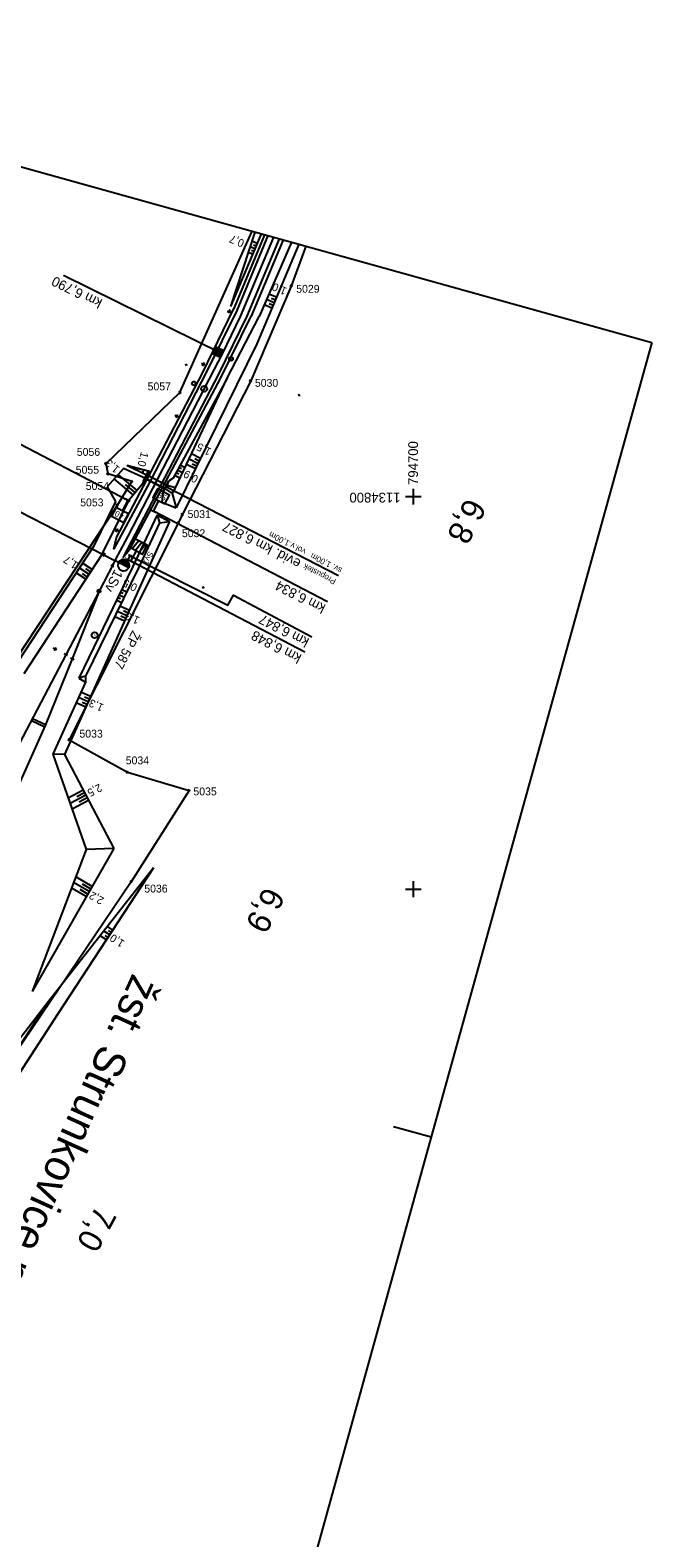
# Model space of a CAD drawing. Extents: x -795094 to -794639, y -1135368 to -1134681.
# Drawn here: x -794797.7 to -794639.2, y -1135065.2 to -1134681.2 of the extents above; entities that cross this region are included whole.
import ezdxf

# ---------------------------------------------------------------- set-up
doc = ezdxf.new("R2010")
doc.units = 0
for name, color, linetype in [('0381KM005-009P - Vrstva 1', 7, 'Continuous'), ('0381KM005-009P - Vrstva 19', 7, 'Continuous'), ('0381KM005-009P - Vrstva 2', 7, 'Continuous'), ('0381KM005-009P - Vrstva 23', 7, 'Continuous'), ('0381KM005-009P - Vrstva 28', 7, 'Continuous'), ('0381KM005-009P - Vrstva 3', 7, 'Continuous'), ('0381KM005-009P - Vrstva 33', 7, 'Continuous'), ('0381KM005-009P - Vrstva 4', 7, 'Continuous'), ('0381KM005-009P - Vrstva 48', 7, 'Continuous'), ('0381KM005-009P - Vrstva 49', 7, 'Continuous'), ('0381KM005-009P - Vrstva 5', 7, 'Continuous'), ('0381KM005-009P - Vrstva 51', 7, 'Continuous'), ('0381KM005-009P - Vrstva 6', 7, 'Continuous'), ('0381KM005-009P - Vrstva 7', 7, 'Continuous'), ('formát', 7, 'Continuous'), ('krizky_1000 - souradnice', 7, 'Continuous'), ('krizky_1000 - Vrstva 1', 7, 'Continuous'), ('szdc - hran DP', 7, 'Continuous'), ('szdc - szdc_cislo', 7, 'Continuous'), ('szdc - szdc_krizek', 7, 'Continuous'), ('vyt_sit - stávající', 7, 'Continuous')]:
    doc.layers.add(name, color=color, linetype=linetype)

msp = doc.modelspace()

# ---------------------------------------------------------------- linework, layer by layer
at = {"layer": '0381KM005-009P - Vrstva 1'}
for points in [[(-794735.66, -1134733.94), (-794744.1, -1134754.13), (-794748.76, -1134763.69), (-794750.73, -1134767.6), (-794757.62, -1134780.92)], [(-794757.62, -1134780.92), (-794772.8, -1134810.07), (-794776.07, -1134816.32)], [(-794776.07, -1134816.32), (-794776.43, -1134817.02), (-794780.11, -1134824.07), (-794788.58, -1134840.28)], [(-794776.07, -1134816.32), (-794776.43, -1134817.02), (-794780.11, -1134824.07), (-794786.96, -1134841.36)], [(-794788.58, -1134840.28), (-794803.19, -1134868.16), (-794810.38, -1134881.86), (-794818.66, -1134897.6), (-794826.62, -1134912.5), (-794834.33, -1134926.85), (-794861.92, -1134977.99)], [(-794786.96, -1134841.36), (-794793.84, -1134858.32), (-794800.91, -1134874.12), (-794807.73, -1134887.87), (-794826.52, -1134924.29), (-794833.34, -1134937.13), (-794839.37, -1134947.86), (-794840.75, -1134950.16), (-794846.08, -1134958.61), (-794850.88, -1134965.55), (-794860.1, -1134978.74)]]:
    msp.add_lwpolyline(points, dxfattribs=at)
at = {"layer": '0381KM005-009P - Vrstva 19'}
for p, q in [((-794767.26, -1134793.5), (-794768.87, -1134796.52)), ((-794768.87, -1134796.52), (-794768.27, -1134795.41)), ((-794768.27, -1134795.41), (-794767.82, -1134794.57)), ((-794768.27, -1134795.41), (-794768.27, -1134795.41)), ((-794763.3, -1134797.99), (-794768.27, -1134795.41)), ((-794768.27, -1134795.41), (-794763.33, -1134798.06)), ((-794767.82, -1134794.57), (-794767.26, -1134793.5)), ((-794767.82, -1134794.57), (-794767.82, -1134794.57)), ((-794762.85, -1134797.19), (-794767.82, -1134794.57)), ((-794762.89, -1134797.15), (-794767.82, -1134794.57)), ((-794763.85, -1134798.98), (-794762.37, -1134796.11)), ((-794763.3, -1134797.99), (-794763.85, -1134798.98)), ((-794762.89, -1134797.15), (-794763.33, -1134798.06)), ((-794763.33, -1134798.06), (-794763.3, -1134797.99)), ((-794719.1, -1134820.2), (-794763.06, -1134797.51)), ((-794762.85, -1134797.19), (-794762.89, -1134797.15)), ((-794762.37, -1134796.11), (-794762.85, -1134797.19))]:
    msp.add_line(p, q, dxfattribs=at)
at = {"layer": '0381KM005-009P - Vrstva 2'}
for p, q in [((-794815.95, -1134795.81), (-794776.07, -1134816.32)), ((-794775.14, -1134816.79), (-794776.07, -1134816.32)), ((-794772.54, -1134818.13), (-794775.14, -1134816.79)), ((-794774.93, -1134816.49), (-794774.77, -1134816.98)), ((-794774.61, -1134816.22), (-794774.29, -1134817.23)), ((-794774.26, -1134816.06), (-794773.81, -1134817.48)), ((-794773.89, -1134816), (-794773.33, -1134817.72)), ((-794773.47, -1134816.05), (-794772.86, -1134817.97)), ((-794773, -1134816.26), (-794772.46, -1134817.95)), ((-794772.54, -1134818.13), (-794772.54, -1134818.13)), ((-794780.11, -1134824.07), (-794786.96, -1134841.36)), ((-794788.14, -1134840.51), (-794789.03, -1134840.05)), ((-794786.49, -1134841.55), (-794787.42, -1134841.18))]:
    msp.add_line(p, q, dxfattribs=at)
for points in [[(-794776.07, -1134816.32), (-794776.43, -1134817.02), (-794780.11, -1134824.07), (-794788.58, -1134840.28)], [(-794776.64, -1134817.99), (-794776.43, -1134817.02), (-794777.1, -1134817.76)]]:
    msp.add_lwpolyline(points, dxfattribs=at)
msp.add_circle((-794780.11, -1134824.07), 0.4, dxfattribs=at)
for start, end in [(152.7102, 333.1797), (332.7997, 152.7606)]:
    msp.add_arc((-794773.84, -1134817.46), 1.46, start, end, dxfattribs=at)
at = {"layer": '0381KM005-009P - Vrstva 28'}
msp.add_line((-794746.44, -1134764.88), (-794746.48, -1134764.97), dxfattribs=at)
msp.add_circle((-794746.46, -1134764.93), 0.5, dxfattribs=at)
at = {"layer": '0381KM005-009P - Vrstva 3'}
for p, q in [((-794748.76, -1134763.69), (-794789.21, -1134743.71)), ((-794750.81, -1134763.35), (-794750.63, -1134763.89)), ((-794750.58, -1134762.87), (-794750.15, -1134764.12)), ((-794750.35, -1134762.39), (-794749.67, -1134764.36)), ((-794750.12, -1134761.92), (-794749.2, -1134764.59)), ((-794749.64, -1134762.15), (-794748.96, -1134764.11)), ((-794749.16, -1134762.38), (-794748.73, -1134763.64)), ((-794748.69, -1134762.61), (-794748.5, -1134763.16))]:
    msp.add_line(p, q, dxfattribs=at)
msp.add_lwpolyline([(-794748.32, -1134762.79), (-794749.2, -1134764.59), (-794750.99, -1134763.71), (-794750.12, -1134761.92)], close=True, dxfattribs=at)
at = {"layer": '0381KM005-009P - Vrstva 33'}
msp.add_line((-794768.83, -1134796.2), (-794767.55, -1134793.7), dxfattribs=at)
at = {"layer": '0381KM005-009P - Vrstva 4'}
for points in [[(-794737.95, -1134733.31), (-794745.79, -1134752.29)], [(-794737.06, -1134733.55), (-794744.97, -1134752.65)], [(-794734.21, -1134734.35), (-794742.45, -1134754.09)], [(-794733.14, -1134734.64), (-794741.33, -1134754.03)], [(-794744.97, -1134752.65), (-794752.57, -1134767.89), (-794767.17, -1134796.25), (-794776.32, -1134813.35), (-794775.69, -1134810.46), (-794767.89, -1134795.76), (-794753.75, -1134768.59), (-794745.79, -1134752.29)], [(-794742.45, -1134754.09), (-794749.67, -1134768.83), (-794764.43, -1134797.23), (-794773.98, -1134815.47), (-794772.27, -1134813.39), (-794763.8, -1134797.42), (-794749.03, -1134769.75), (-794741.33, -1134754.03)]]:
    msp.add_lwpolyline(points, dxfattribs=at)
at = {"layer": '0381KM005-009P - Vrstva 48'}
for p, q in [((-794740.39, -1134736.92), (-794741.61, -1134736.4)), ((-794740.68, -1134737.61), (-794741.26, -1134737.36)), ((-794739.8, -1134735.54), (-794741.14, -1134734.97)), ((-794740.09, -1134736.23), (-794740.73, -1134735.96)), ((-794740.97, -1134738.3), (-794742.08, -1134737.83)), ((-794734.87, -1134749.26), (-794736.81, -1134748.45)), ((-794736.03, -1134752.03), (-794738.01, -1134751.2)), ((-794735.45, -1134750.65), (-794737.41, -1134749.82)), ((-794735.74, -1134751.34), (-794736.72, -1134750.92)), ((-794735.16, -1134749.96), (-794736.13, -1134749.54)), ((-794754.88, -1134791.63), (-794757.17, -1134790.5)), ((-794754.22, -1134790.28), (-794756.53, -1134789.14)), ((-794754.55, -1134790.95), (-794755.7, -1134790.39)), ((-794770.44, -1134798.41), (-794775.25, -1134794.4)), ((-794770.26, -1134792.73), (-794770.4, -1134793.3)), ((-794769.53, -1134792.91), (-794769.62, -1134793.27)), ((-794768.8, -1134793.1), (-794769.03, -1134793.97)), ((-794760.82, -1134794.53), (-794759.43, -1134795.29)), ((-794760.46, -1134793.87), (-794759.79, -1134794.24)), ((-794760.11, -1134793.21), (-794758.79, -1134793.93)), ((-794759.75, -1134792.55), (-794759.11, -1134792.9)), ((-794759.39, -1134791.89), (-794758.15, -1134792.57)), ((-794755.55, -1134792.97), (-794757.81, -1134791.86)), ((-794755.21, -1134792.3), (-794756.35, -1134791.74)), ((-794771.4, -1134799.56), (-794776.25, -1134795.52)), ((-794770.92, -1134798.98), (-794773.33, -1134796.97)), ((-794782.69, -1134819.79), (-794785.16, -1134818.18)), ((-794781.87, -1134818.54), (-794784.33, -1134816.93)), ((-794782.28, -1134819.17), (-794783.51, -1134818.36)), ((-794783.51, -1134821.05), (-794785.98, -1134819.43)), ((-794783.1, -1134820.42), (-794784.34, -1134819.61)), ((-794775.3, -1134825.69), (-794774.65, -1134826)), ((-794774.98, -1134825.01), (-794773.67, -1134825.64)), ((-794774.65, -1134824.34), (-794774, -1134824.65)), ((-794774.33, -1134823.66), (-794773.01, -1134824.29)), ((-794775.63, -1134826.36), (-794774.33, -1134826.99)), ((-794773.01, -1134830.36), (-794775.45, -1134829.27)), ((-794772.39, -1134828.99), (-794774.79, -1134827.92)), ((-794772.7, -1134829.68), (-794773.91, -1134829.14)), ((-794773.62, -1134831.73), (-794776.11, -1134830.61)), ((-794773.32, -1134831.05), (-794774.55, -1134830.49)), ((-794783.49, -1134853.67), (-794785.97, -1134852.55)), ((-794782.87, -1134852.3), (-794785.35, -1134851.19)), ((-794782.26, -1134850.93), (-794784.73, -1134849.82)), ((-794783.18, -1134852.98), (-794784.42, -1134852.43)), ((-794782.56, -1134851.61), (-794783.8, -1134851.06)), ((-794784.18, -1134874.77), (-794788, -1134876.78)), ((-794783.83, -1134875.43), (-794785.79, -1134876.46)), ((-794783.48, -1134876.09), (-794787.5, -1134878.21)), ((-794782.78, -1134877.42), (-794787, -1134879.64)), ((-794783.13, -1134876.76), (-794785.19, -1134877.84)), ((-794782.63, -1134900.58), (-794786.61, -1134898.31)), ((-794781.89, -1134899.28), (-794786.07, -1134896.89)), ((-794782.26, -1134899.93), (-794784.3, -1134898.76)), ((-794783.38, -1134901.88), (-794787.15, -1134899.73)), ((-794783, -1134901.23), (-794784.94, -1134900.12)), ((-794776.57, -1134910.4), (-794777.95, -1134909.49)), ((-794776.98, -1134911.03), (-794777.7, -1134910.55)), ((-794778.21, -1134912.91), (-794779.82, -1134911.86)), ((-794777.39, -1134911.65), (-794778.88, -1134910.67)), ((-794777.8, -1134912.28), (-794778.58, -1134911.77))]:
    msp.add_line(p, q, dxfattribs=at)
at = {"layer": '0381KM005-009P - Vrstva 49'}
for p, q in [((-794740.37, -1134732.63), (-794746.6, -1134751.57)), ((-794738.76, -1134733.08), (-794746.6, -1134751.57)), ((-794729.18, -1134735.74), (-794739.85, -1134761.11)), ((-794731.07, -1134735.22), (-794739.3, -1134754.18)), ((-794747.45, -1134769.82), (-794739.3, -1134754.18)), ((-794739.85, -1134761.11), (-794760.44, -1134802.9)), ((-794757.66, -1134766.37), (-794758.14, -1134766.52)), ((-794757.97, -1134766.21), (-794757.82, -1134766.69)), ((-794747.45, -1134769.82), (-794761.22, -1134795.28)), ((-794760.61, -1134797.81), (-794747.45, -1134769.82)), ((-794728.89, -1134774.12), (-794729.36, -1134774.28)), ((-794729.21, -1134773.96), (-794729.05, -1134774.44)), ((-794773.87, -1134792.87), (-794778.08, -1134797.54)), ((-794768.27, -1134795.41), (-794773.87, -1134792.87)), ((-794773.02, -1134792.01), (-794767.82, -1134794.57)), ((-794773.02, -1134792.01), (-794767.26, -1134793.5)), ((-794768.27, -1134795.41), (-794768.87, -1134796.52)), ((-794767.82, -1134794.57), (-794767.26, -1134793.5)), ((-794761.22, -1134795.28), (-794762.37, -1134796.11)), ((-794778.08, -1134797.54), (-794775.92, -1134801.3)), ((-794772.33, -1134800.68), (-794768.87, -1134796.52)), ((-794763.85, -1134798.98), (-794764.14, -1134801.43)), ((-794762.37, -1134796.11), (-794763.85, -1134798.98)), ((-794763.3, -1134797.99), (-794763.85, -1134798.98)), ((-794763.3, -1134797.99), (-794761.44, -1134799.24)), ((-794762.85, -1134797.19), (-794762.37, -1134796.11)), ((-794760.61, -1134797.81), (-794762.85, -1134797.19)), ((-794761.44, -1134799.24), (-794760.61, -1134797.81)), ((-794761.44, -1134799.24), (-794760.44, -1134802.9)), ((-794775.92, -1134801.3), (-794781.56, -1134812.71)), ((-794779.34, -1134814.68), (-794772.33, -1134800.68)), ((-794764.14, -1134801.43), (-794760.44, -1134802.9)), ((-794765.33, -1134804.62), (-794771.57, -1134817.97)), ((-794764.66, -1134806.73), (-794770.02, -1134818.19)), ((-794762.15, -1134806.37), (-794768.04, -1134819.3)), ((-794765.33, -1134804.62), (-794764.66, -1134806.73)), ((-794765.33, -1134804.62), (-794762.15, -1134806.37)), ((-794764.66, -1134806.73), (-794762.15, -1134806.37)), ((-794781.56, -1134812.71), (-794806.26, -1134850.22)), ((-794779.34, -1134814.68), (-794799.26, -1134845.15)), ((-794771.57, -1134817.97), (-794785.26, -1134846.3)), ((-794770.02, -1134818.19), (-794783.54, -1134845.78)), ((-794768.04, -1134819.3), (-794788.91, -1134865.74)), ((-794753.32, -1134823.06), (-794753.8, -1134823.21)), ((-794753.64, -1134822.9), (-794753.49, -1134823.38)), ((-794783.58, -1134847.29), (-794791.9, -1134865.62)), ((-794783.54, -1134845.78), (-794785.26, -1134846.3)), ((-794785.26, -1134846.3), (-794783.58, -1134847.29)), ((-794783.54, -1134845.78), (-794783.58, -1134847.29)), ((-794791.9, -1134865.62), (-794783.41, -1134889.91)), ((-794788.91, -1134865.74), (-794791.9, -1134865.62)), ((-794788.91, -1134865.74), (-794776.38, -1134889.62)), ((-794776.38, -1134889.62), (-794797.15, -1134926.02)), ((-794783.41, -1134889.91), (-794797.15, -1134926.02)), ((-794776.38, -1134889.62), (-794783.41, -1134889.91)), ((-794766.19, -1134894.56), (-794792.99, -1134928.57)), ((-794766.19, -1134894.56), (-794790.5, -1134931.65)), ((-794792.99, -1134928.57), (-794819.56, -1134969.3)), ((-794792.99, -1134928.57), (-794819.08, -1134962.42)), ((-794790.5, -1134931.65), (-794824.29, -1134983.58))]:
    msp.add_line(p, q, dxfattribs=at)
at = {"layer": '0381KM005-009P - Vrstva 5'}
for p, q in [((-794808.79, -1134782.22), (-794772.81, -1134800.95)), ((-794772.14, -1134801.3), (-794773.47, -1134800.61)), ((-794766.9, -1134803.37), (-794765.57, -1134804.07)), ((-794721.88, -1134826.8), (-794766.23, -1134803.72))]:
    msp.add_line(p, q, dxfattribs=at)
for points in [[(-794766.23, -1134803.72), (-794764.85, -1134801.06), (-794763.3, -1134801.87), (-794762.14, -1134799.65), (-794765.25, -1134798.03), (-794766.4, -1134800.25), (-794764.85, -1134801.06)], [(-794772.81, -1134800.95), (-794774.19, -1134803.61), (-794775.74, -1134802.81), (-794776.9, -1134805.02), (-794773.79, -1134806.64), (-794772.64, -1134804.42), (-794774.19, -1134803.61)]]:
    msp.add_lwpolyline(points, dxfattribs=at)
at = {"layer": '0381KM005-009P - Vrstva 51'}
msp.add_lwpolyline([(-794871.74, -1135021.34), (-794845.86, -1135006.13), (-794837.37, -1134998.39), (-794824.29, -1134983.58), (-794790.5, -1134931.65), (-794766.19, -1134894.56)], dxfattribs=at)
at = {"layer": '0381KM005-009P - Vrstva 6'}
for p, q in [((-794773.1, -1134816.84), (-794772.18, -1134815.08)), ((-794771.74, -1134815.31), (-794772.62, -1134814.85))]:
    msp.add_line(p, q, dxfattribs=at)
msp.add_lwpolyline([(-794772.18, -1134815.08), (-794747.28, -1134827.67), (-794745.87, -1134825.09), (-794725.88, -1134835.7)], dxfattribs=at)
at = {"layer": '0381KM005-009P - Vrstva 7'}
for p, q in [((-794747.36, -1134752.67), (-794746.44, -1134753.06)), ((-794747.09, -1134753.33), (-794746.71, -1134752.4)), ((-794753.12, -1134766.56), (-794754.01, -1134766.1)), ((-794753.33, -1134765.88), (-794753.79, -1134766.77)), ((-794755.87, -1134771.14), (-794755.92, -1134771.23)), ((-794759.86, -1134779.78), (-794760.75, -1134779.32)), ((-794760.07, -1134779.1), (-794760.53, -1134779.99)), ((-794775.17, -1134808.86), (-794776.06, -1134808.4)), ((-794775.38, -1134808.18), (-794775.84, -1134809.07)), ((-794778.43, -1134815.06), (-794779.32, -1134814.6)), ((-794778.65, -1134814.39), (-794779.11, -1134815.27)), ((-794771.69, -1134813.25), (-794770.09, -1134811.26)), ((-794769.2, -1134811.73), (-794770.8, -1134813.71)), ((-794769.92, -1134814.17), (-794768.32, -1134812.19)), ((-794772.64, -1134816.14), (-794771.31, -1134816.83)), ((-794727.67, -1134839.67), (-794771.97, -1134816.49)), ((-794790.89, -1134839.08), (-794791.78, -1134838.62)), ((-794791.11, -1134838.41), (-794791.57, -1134839.3)), ((-794797.09, -1134856.53), (-794793.74, -1134858.08)), ((-794797.37, -1134857.06), (-794793.96, -1134858.64))]:
    msp.add_line(p, q, dxfattribs=at)
msp.add_lwpolyline([(-794771.97, -1134816.49), (-794770.58, -1134813.83), (-794769.03, -1134814.64), (-794767.87, -1134812.42), (-794770.97, -1134810.8), (-794772.13, -1134813.02), (-794770.58, -1134813.83)], dxfattribs=at)
for centre, radius in [((-794755.9, -1134771.19), 0.5), ((-794753.29, -1134772.54), 0.75)]:
    msp.add_circle(centre, radius, dxfattribs=at)
at = {"layer": 'formát'}
for p, q in [((-794925.31, -1134681.22), (-794639.16, -1134760.77)), ((-794639.16, -1134760.77), (-794695.41, -1134963.1)), ((-794705.05, -1134960.42), (-794695.41, -1134963.1)), ((-794705.05, -1134960.42), (-794695.41, -1134963.1)), ((-794695.41, -1134963.1), (-794751.67, -1135165.42))]:
    msp.add_line(p, q, dxfattribs=at)
at = {"layer": 'krizky_1000 - Vrstva 1'}
for points in [[(-794700, -1134798), (-794700, -1134802)], [(-794702, -1134800), (-794698, -1134800)], [(-794700, -1134898), (-794700, -1134902)], [(-794702, -1134900), (-794698, -1134900)]]:
    msp.add_lwpolyline(points, dxfattribs=at)
at = {"layer": 'szdc - hran DP'}
for p, q in [((-794759.53, -1134773.54), (-794741.05, -1134732.44)), ((-794727.43, -1134736.23), (-794731.15, -1134746.39)), ((-794731.15, -1134746.39), (-794741.45, -1134770.5)), ((-794741.45, -1134770.5), (-794758.9, -1134804.63)), ((-794778.33, -1134791.56), (-794759.53, -1134773.54)), ((-794777.82, -1134794.18), (-794778.33, -1134791.56)), ((-794771.78, -1134796.16), (-794777.82, -1134794.18)), ((-794775.44, -1134802.2), (-794771.78, -1134796.16)), ((-794808.02, -1134851.51), (-794775.44, -1134802.2)), ((-794759.9, -1134806.76), (-794787.72, -1134861.99)), ((-794758.9, -1134804.63), (-794759.9, -1134806.76)), ((-794787.72, -1134861.99), (-794772.84, -1134870.22)), ((-794772.84, -1134870.22), (-794757.13, -1134874.85)), ((-794757.13, -1134874.85), (-794771.93, -1134898.11)), ((-794771.93, -1134898.11), (-794808.62, -1134952.39))]:
    msp.add_line(p, q, dxfattribs=at)
at = {"layer": 'szdc - szdc_krizek'}
for p, q in [((-794730.89, -1134746.66), (-794731.42, -1134746.12)), ((-794731.42, -1134746.66), (-794730.89, -1134746.12)), ((-794741.19, -1134770.77), (-794741.72, -1134770.24)), ((-794741.72, -1134770.77), (-794741.19, -1134770.24)), ((-794759.27, -1134773.8), (-794759.8, -1134773.28)), ((-794759.8, -1134773.8), (-794759.27, -1134773.28)), ((-794778.07, -1134791.82), (-794778.6, -1134791.29)), ((-794778.6, -1134791.82), (-794778.07, -1134791.29)), ((-794777.56, -1134794.45), (-794778.09, -1134793.92)), ((-794778.09, -1134794.45), (-794777.56, -1134793.92)), ((-794771.52, -1134796.43), (-794772.05, -1134795.9)), ((-794772.05, -1134796.43), (-794771.52, -1134795.9)), ((-794775.18, -1134802.47), (-794775.71, -1134801.94)), ((-794775.71, -1134802.47), (-794775.18, -1134801.94)), ((-794759.64, -1134807.03), (-794760.17, -1134806.5)), ((-794760.17, -1134807.03), (-794759.64, -1134806.5)), ((-794758.64, -1134804.9), (-794759.17, -1134804.36)), ((-794759.17, -1134804.9), (-794758.64, -1134804.36)), ((-794787.46, -1134862.26), (-794787.99, -1134861.73)), ((-794787.99, -1134862.26), (-794787.46, -1134861.73)), ((-794772.58, -1134870.49), (-794773.11, -1134869.96)), ((-794773.11, -1134870.49), (-794772.58, -1134869.96)), ((-794756.86, -1134875.11), (-794757.4, -1134874.58)), ((-794757.4, -1134875.11), (-794756.86, -1134874.58)), ((-794771.67, -1134898.38), (-794772.2, -1134897.84)), ((-794772.2, -1134898.38), (-794771.67, -1134897.84))]:
    msp.add_line(p, q, dxfattribs=at)
at = {"layer": 'vyt_sit - stávající'}
msp.add_line((-794781.21, -1134835.29), (-794781.25, -1134835.37), dxfattribs=at)
msp.add_circle((-794781.23, -1134835.33), 0.756, dxfattribs=at)

# ---------------------------------------------------------------- texts
at = {"layer": '0381KM005-009P - Vrstva 19'}
for s, height, p in [('evid. km 6,827', 2.5, (-794728.46, -1134816.29)), ('sv. 1,00m   vol.v.1,00m', 1.5, (-794717.99, -1134818.3)), ('Propustek', 1.5, (-794719.55, -1134821.16))]:
    msp.add_text(s, height=height, rotation=152.7057, dxfattribs=at).set_placement(p)
at = {"layer": '0381KM005-009P - Vrstva 2'}
msp.add_text('1Sv', height=2.5, rotation=242.4084, dxfattribs=at).set_placement((-794776.11, -1134818.38))
at = {"layer": '0381KM005-009P - Vrstva 23'}
msp.add_text('žst. Strunkovice nad Volyňkou', height=8, rotation=245.663, dxfattribs=at).set_placement((-794771.54, -1134921.22))
at = {"layer": '0381KM005-009P - Vrstva 3'}
msp.add_text('km 6,790', height=2.5, rotation=153.7108, dxfattribs=at).set_placement((-794779.06, -1134749.9))
at = {"layer": '0381KM005-009P - Vrstva 48'}
for s, rotation, p in [('0,7', 157.0225, (-794742.9, -1134734.77)), ('1,0', 157.1828, (-794732.04, -1134746.95)), ('1,5', 153.7759, (-794751.28, -1134787.9)), ('1,3', 140.2012, (-794774.66, -1134792.71)), ('1,0', 255.4428, (-794769.39, -1134788.47)), ('0,9', 151.5692, (-794754.62, -1134794.92)), ('1,7', 146.832, (-794785.24, -1134816.96)), ('0,5', 154.2119, (-794770.15, -1134822.51)), ('1,3', 155.7895, (-794769.58, -1134830.83)), ('1,3', 155.7895, (-794778.72, -1134853.04)), ('2,5', 207.6821, (-794780.03, -1134873.07)), ('2,2', 150.2833, (-794778.67, -1134902.33)), ('1,0', 146.755, (-794773.41, -1134913.32))]:
    msp.add_text(s, height=2, rotation=rotation, dxfattribs=at).set_placement(p)
at = {"layer": '0381KM005-009P - Vrstva 5'}
for s, height, rotation, p in [('55', 1.5, 332.5023, (-794765.41, -1134800.15)), ('40', 1.5, 152.5023, (-794773.63, -1134804.52)), ('km 6,834', 2.5, 152.5023, (-794722.13, -1134827.68))]:
    msp.add_text(s, height=height, rotation=rotation, dxfattribs=at).set_placement(p)
at = {"layer": '0381KM005-009P - Vrstva 6'}
for s, height, rotation, p in [('Sv1', 1.5, 242.5023, (-794767.44, -1134813.81)), ('  A ', 1, 242.3746, (-794773.07, -1134814.62)), ('km 6,847', 2.5, 152.3746, (-794726.31, -1134836.27))]:
    msp.add_text(s, height=height, rotation=rotation, dxfattribs=at).set_placement(p)
at = {"layer": '0381KM005-009P - Vrstva 7'}
for s, height, rotation, p in [('6,8', 6, 242.6352, (-794686.43, -1134800.02)), ('km 6,848', 2.5, 152.3746, (-794728.26, -1134840.39)), ('6,9', 6, 242.3222, (-794737.76, -1134899.06)), ('7,0', 6, 241.6619, (-794780.73, -1134980.29))]:
    msp.add_text(s, height=height, rotation=rotation, dxfattribs=at).set_placement(p)
at = {"layer": 'krizky_1000 - souradnice'}
for s, rotation, p in [('794700', 90, (-794698.79, -1134797.05)), ('1134800', 180, (-794703.26, -1134799.02))]:
    msp.add_text(s, height=2.5, rotation=rotation, dxfattribs=at).set_placement(p)
at = {"layer": 'szdc - szdc_cislo'}
for s, p in [('5029', (-794729.84, -1134748.09)), ('5057', (-794767.73, -1134772.95)), ('5030', (-794740.38, -1134772.05)), ('5056', (-794785.78, -1134789.63)), ('5055', (-794786.06, -1134794.18)), ('5054', (-794783.5, -1134798.31)), ('5053', (-794784.92, -1134802.5)), ('5031', (-794757.55, -1134805.48)), ('5032', (-794758.98, -1134810.34)), ('5033', (-794785.11, -1134861.4)), ('5034', (-794773.31, -1134868.2)), ('5035', (-794756.06, -1134876.1)), ('5036', (-794768.58, -1134900.85))]:
    msp.add_text(s, height=2, dxfattribs=at).set_placement(p)
at = {"layer": 'vyt_sit - stávající'}
msp.add_text('ŽP 587', height=2.4, rotation=242.405, dxfattribs=at).set_placement((-794771.57, -1134833.95))

doc.saveas('drawing.dxf')
